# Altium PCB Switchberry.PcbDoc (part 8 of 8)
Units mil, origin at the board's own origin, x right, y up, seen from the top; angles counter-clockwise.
Board outline 4500 x 3824.8 mil, 6 copper layers (L01-TOP, L02-GND, L03-SIG, L04-SIG, L05-GND, L06-BOT), stack 49.214 mil thick; 431 components, 322 nets, 1699 pads, 1274 vias.
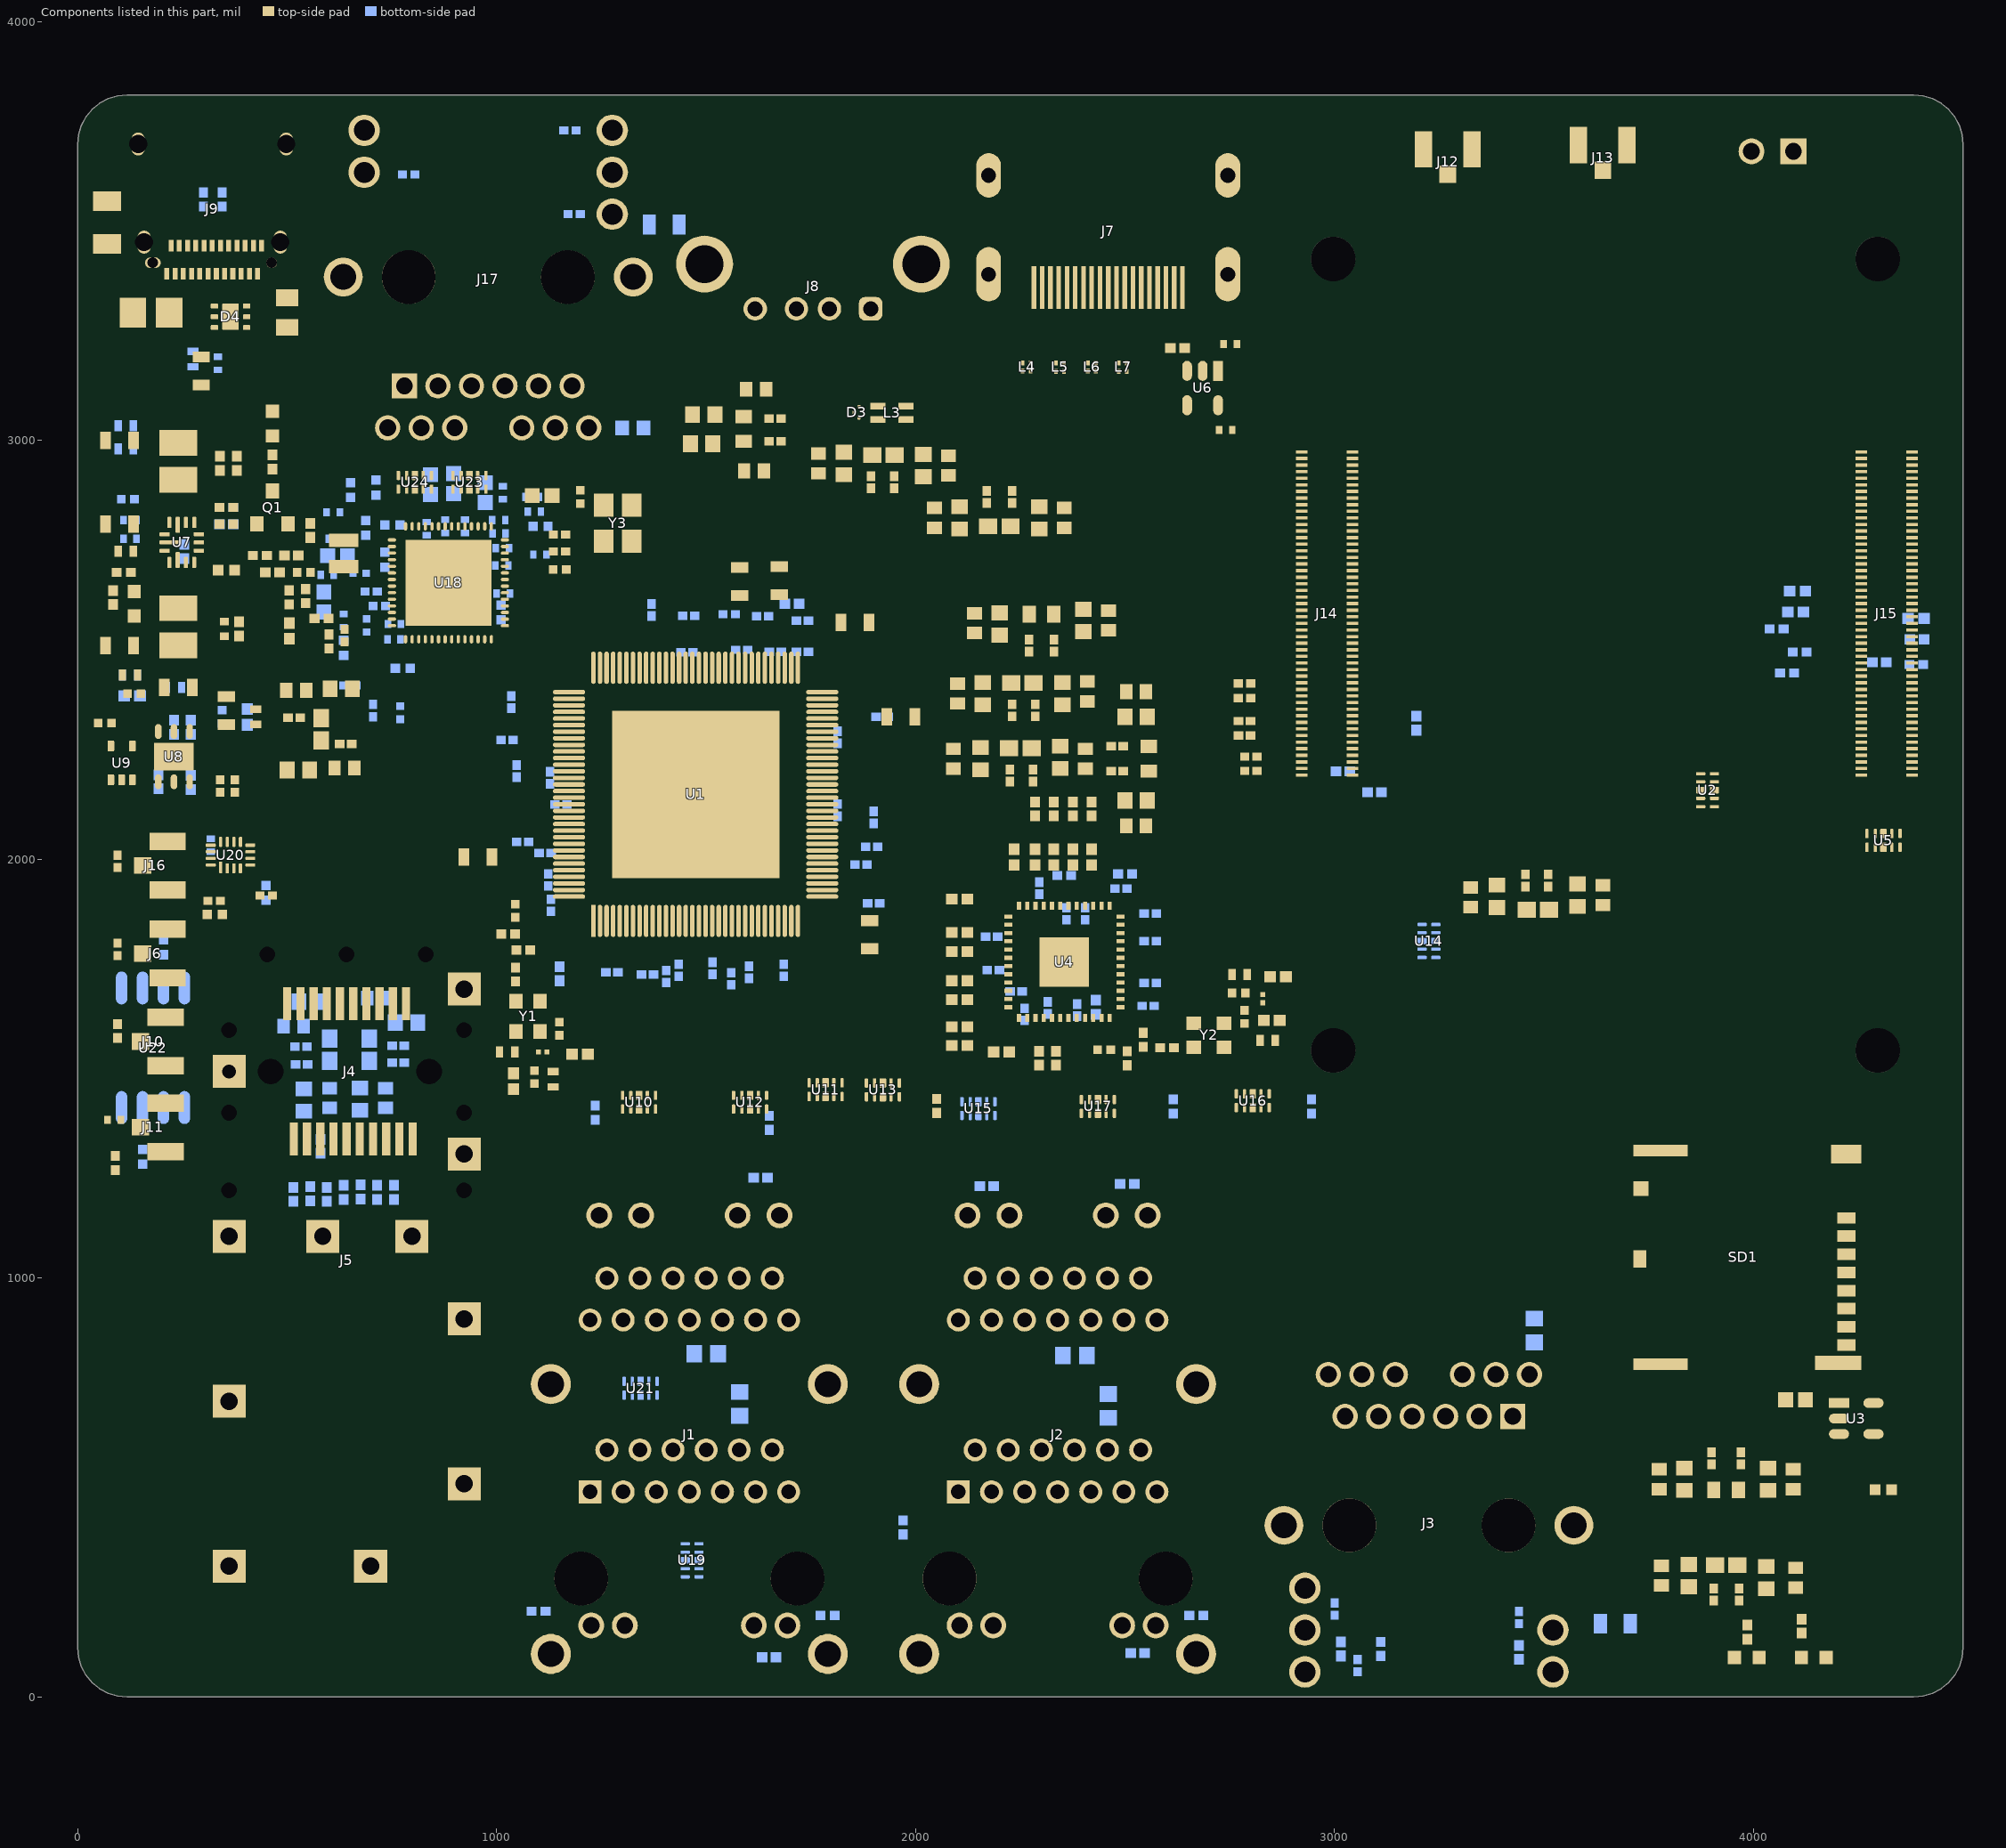
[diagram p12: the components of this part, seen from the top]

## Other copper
L01-TOP:
  pour cut-out: 741.47,2797.18 1025.75,2797.18 1025.75,2525.16 741.47,2525.16
  pour cut-out: 585,2760 585,2677.76 683.94,2677.76 683.94,2760
  pour cut-out: 580,3912.76 1402.44,3912.76 1402.44,2960 580,2960
  pour cut-out: 295,1345 295,1829.33 995.38,1829.33 995.38,-225 285,-225 285,60
  pour cut-out: 975,1365 3645,1365 3645,-100 975,-100 975,100
  pour cut-out: 1420.55,3833.46 2089.45,3833.46 2089.45,3266.54 1420.55,3266.54
  pour cut-out: 2136.85,3821.69 2782.52,3821.69 2782.52,3305.94 2136.85,3305.94 2136.85,3812.05
  pour cut-out: 1172.82,2450 1777.18,2450 1777.18,1852.82 1172.82,1852.82
  pour cut-out: 2207.36,1725.47 2207.36,1902.64 2502.64,1902.64 2502.64,1607.36 2204.8,1607.36 2204.8,1646.73
  pour cut-out: 3700,760 3700,1360 4280.91,1360 4280.91,760

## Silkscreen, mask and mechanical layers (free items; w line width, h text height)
Top Overlay:
  lines w5: 2857.39,3454.08 2857.39,1502.62 2863.57,1482.25 2878.3,1454.7 2892.99,1436.8 2910.88,1422.11 2931.3,1411.2 2953.46,1404.48 2976.5,1402.21 4315.08,1402.21 4338.13,1404.48 4360.28,1411.2 4380.7,1422.11 4398.6,1436.8 4413.29,1454.7 4424.2,1475.12 4430.93,1497.28 4433.2,1520.32 4433.2,3471.78 4430.93,3494.82 4424.2,3516.98 4413.29,3537.4 4398.6,3555.3 4380.7,3569.98 4360.28,3580.9 4338.13,3587.62 4315.08,3589.89 2976.5,3589.89 2953.46,3587.62 2931.3,3580.9 2910.88,3569.98 2892.99,3555.3 2878.3,3537.4 2863.57,3509.84 2857.39,3489.48
Bottom Overlay:
  text "Switchberry V2 / Julian St. James / Ahmad Byagowi / Jeff Geerling" at 4070,2975 h60
Mechanical 1:
  lines w20: 2608.27,0 2631.31,2.27 2653.47,8.99 2673.89,19.9 2691.78,34.59 2706.47,52.49 2717.39,72.91 2724.11,95.07 2726.38,118.11 2726.38,1456.69 2724.11,1479.73 2717.39,1501.89 2706.47,1522.31 2691.78,1540.21 2673.89,1554.9 2653.47,1565.81 2631.31,1572.53 2608.27,1574.8 118.11,1574.8 95.07,1572.53 72.91,1565.81 52.49,1554.9 34.59,1540.21 19.9,1522.31 8.99,1501.89 2.27,1479.73 0,1456.69 0,118.11 2.27,95.07 8.99,72.91 19.9,52.49 34.59,34.59 52.49,19.9 72.91,8.99 95.07,2.27 118.11,0 2618.11,0
Board Shape:
  the board outline again, w10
